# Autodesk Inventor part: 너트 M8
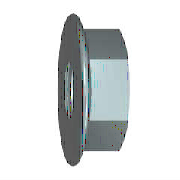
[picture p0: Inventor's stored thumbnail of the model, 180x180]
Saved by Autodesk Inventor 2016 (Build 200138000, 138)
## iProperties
Created: 2015-09
Part Number: 너트 M8
Material: 스테인리스강
Description: 플랜지붙이 6각 너트 - 일반 스레드
Document SubType Name: Modeling
Standard: ISO 4161
Designer: mduedu
Standard Revision: 2판 1999-03-15
Standards Organization: ISO
Language: ko-KR
Size Designation: M8
Categories: <MemberInstance><Categories><Category DisplayName="조임쇠" InternalName="e4da775c-781d-43d5-af7c-5136215cf5a6" Mnemonic="FSTN"><Category DisplayName="너트" InternalN
Density: 8.08 g/cm^3
Appearance: 기본값
Author: mduedu
IsCustomPart: 1
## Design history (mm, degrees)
sketch "스케치1"
  geometry: L1 (-1.844, 0)-(9.641, 0) reference; L2 (3.107, 6.5)-(2.288, 8.257); L3 (3.107, 6.5)-(8, 6.5); L4 (8, 6.5)-(8, 0); L5 (3.107, 6.5)-(3.107, 0); L6 (0, -1.835)-(0, 11.01) reference; A1 r 1.2 centre (1.2, 7.75) between (2.288, 8.257) and (0, 7.75); 1 further point
  constraints: 8 end point, 3 point on line, 2 perpendicular, 2 point on circle, 2 tangent, 1 centre point, 1 parallel
  dimensions: "d2" = 13 diameter of L3 L1 (= SW); "d4" = 17.9 dimension on A1 L1 (= LADI); "d5" = 1.2 radius of A1 (= PHH); "d15" = 8 distance between parallel lines of L4 L6 (= KOH); "d16" = 25 deg angle of L6 L2 (= KEWI)
revolve "링" sketch "스케치1" stored, may be unused: angle "d8" = 90 deg
sketch "스케치2"
  geometry: L1 (-6.5, -3.753)-(-6.5, 3.753); L2 (-6.5, 3.753)-(0, 7.506); L3 (0, 7.506)-(6.5, 3.753); L4 (6.5, 3.753)-(6.5, -3.753); L5 (6.5, -3.753)-(0, -7.506); L6 (0, -7.506)-(-6.5, -3.753); C1 r 4.9 at (0, 0); C2 r 7.75 at (0, 0) reference; 1 further point
  constraints: 12 end point, 1 centre point, 1 coincident, 1 vertical, 11 other
  dimensions: "d6" = 15.01111 distance of L5.end L2.end (= 1.1547 x SW)
extrude "본체" join sketch "스케치2" distance "d7" = 8 (= KOH); taper "d9" = 0 deg
sketch "스케치3"
  geometry: L1 (2.638, 7.506)-(8, 7.506) reference; L2 (8, 3.753)-(8, 7.506) reference; L3 (0, -7.75)-(0, 7.75) reference; L4 (-1.6, 0)-(9.6, 0) reference; L5 (7.419, 7.506)-(8, 6.5)
  constraints: 2 end point, 2 point on line
  dimensions: "d10" = 30 deg angle of L2 L5 (= ANG1); "d11" = 13 diameter of L5.end L4 (= SW0)
revolve "모따기1" sketch "스케치3" stored, may be unused: angle "d24" = 90 deg
sketch "스케치4"
  geometry: C1 r 7.75 at (0, 0) reference; 1 further point
  constraints: 1 coincident
hole "스레드" sketch "스케치4" at (0, 0) diameter "d25" = 6.647; stored, may be unused: countersink angle "d29" = 82 deg, drill point angle "d31" = 118 deg; dims "d26" = 6, "d27" = 4, "d28" = 2, "d30" = 8
workaxis "Work Axis1"
workplane "Work Plane1"
body "Solid1"
chamfer "모따기2" distance "d12" = 0.67658 (= -0.5 x GD1 + 0.5 x NND); stored, may be unused: angle "d13" = 30 deg, second distance "d46" = 0.67658 (= -0.5 x GD1 + 0.5 x NND)
chamfer "모따기3" distance "d51" = 0.67658 (= -0.5 x GD1 + 0.5 x NND); stored, may be unused: second distance "d52" = 2, angle "d53" = 45 deg
other parameters: "ANG1" = 30 deg [user parameter; used in 1 equation term], "KEWI" = 25 deg [user parameter; used in 1 equation term], "NND" = 8 [user parameter; used in 4 equation terms], "LADI" = 17.9 [user parameter; used in 2 equation terms], "SW" = 13 [user parameter; used in 3 equation terms], "PHH" = 1.2 [user parameter; used in 3 equation terms], "KOH" = 8 (= NND) [user parameter; used in 2 equation terms], "SW0" = 13 [user parameter; used in 1 equation term], "GD1" = 6.64684 (computed from THREADDIA, PTC, TOA) [user parameter; used in 3 equation terms], "d1" = 17.9 (= LADI), "d3" = 1.2 (= PHH), "d45" = 0, "d47" = 0, "d49" = 0, "d54" = 0, "GUL" = 0.67658 (= 0.541266 x PTC) [user parameter], "TPU" = 8 (computed from PTC) [user parameter], "RR" = 1.2 (= PHH) [user parameter], "THREADDIA" = 8 [user parameter; used in 1 equation term], "TOA" = 30 deg [user parameter; used in 1 equation term], "PTC" = 1.25 [user parameter; used in 4 equation terms], "GAL" = 0.67658 (= 0.541266 x PTC) [user parameter], "E0" = 15.015 (= 1.155 x SW) [user parameter]
